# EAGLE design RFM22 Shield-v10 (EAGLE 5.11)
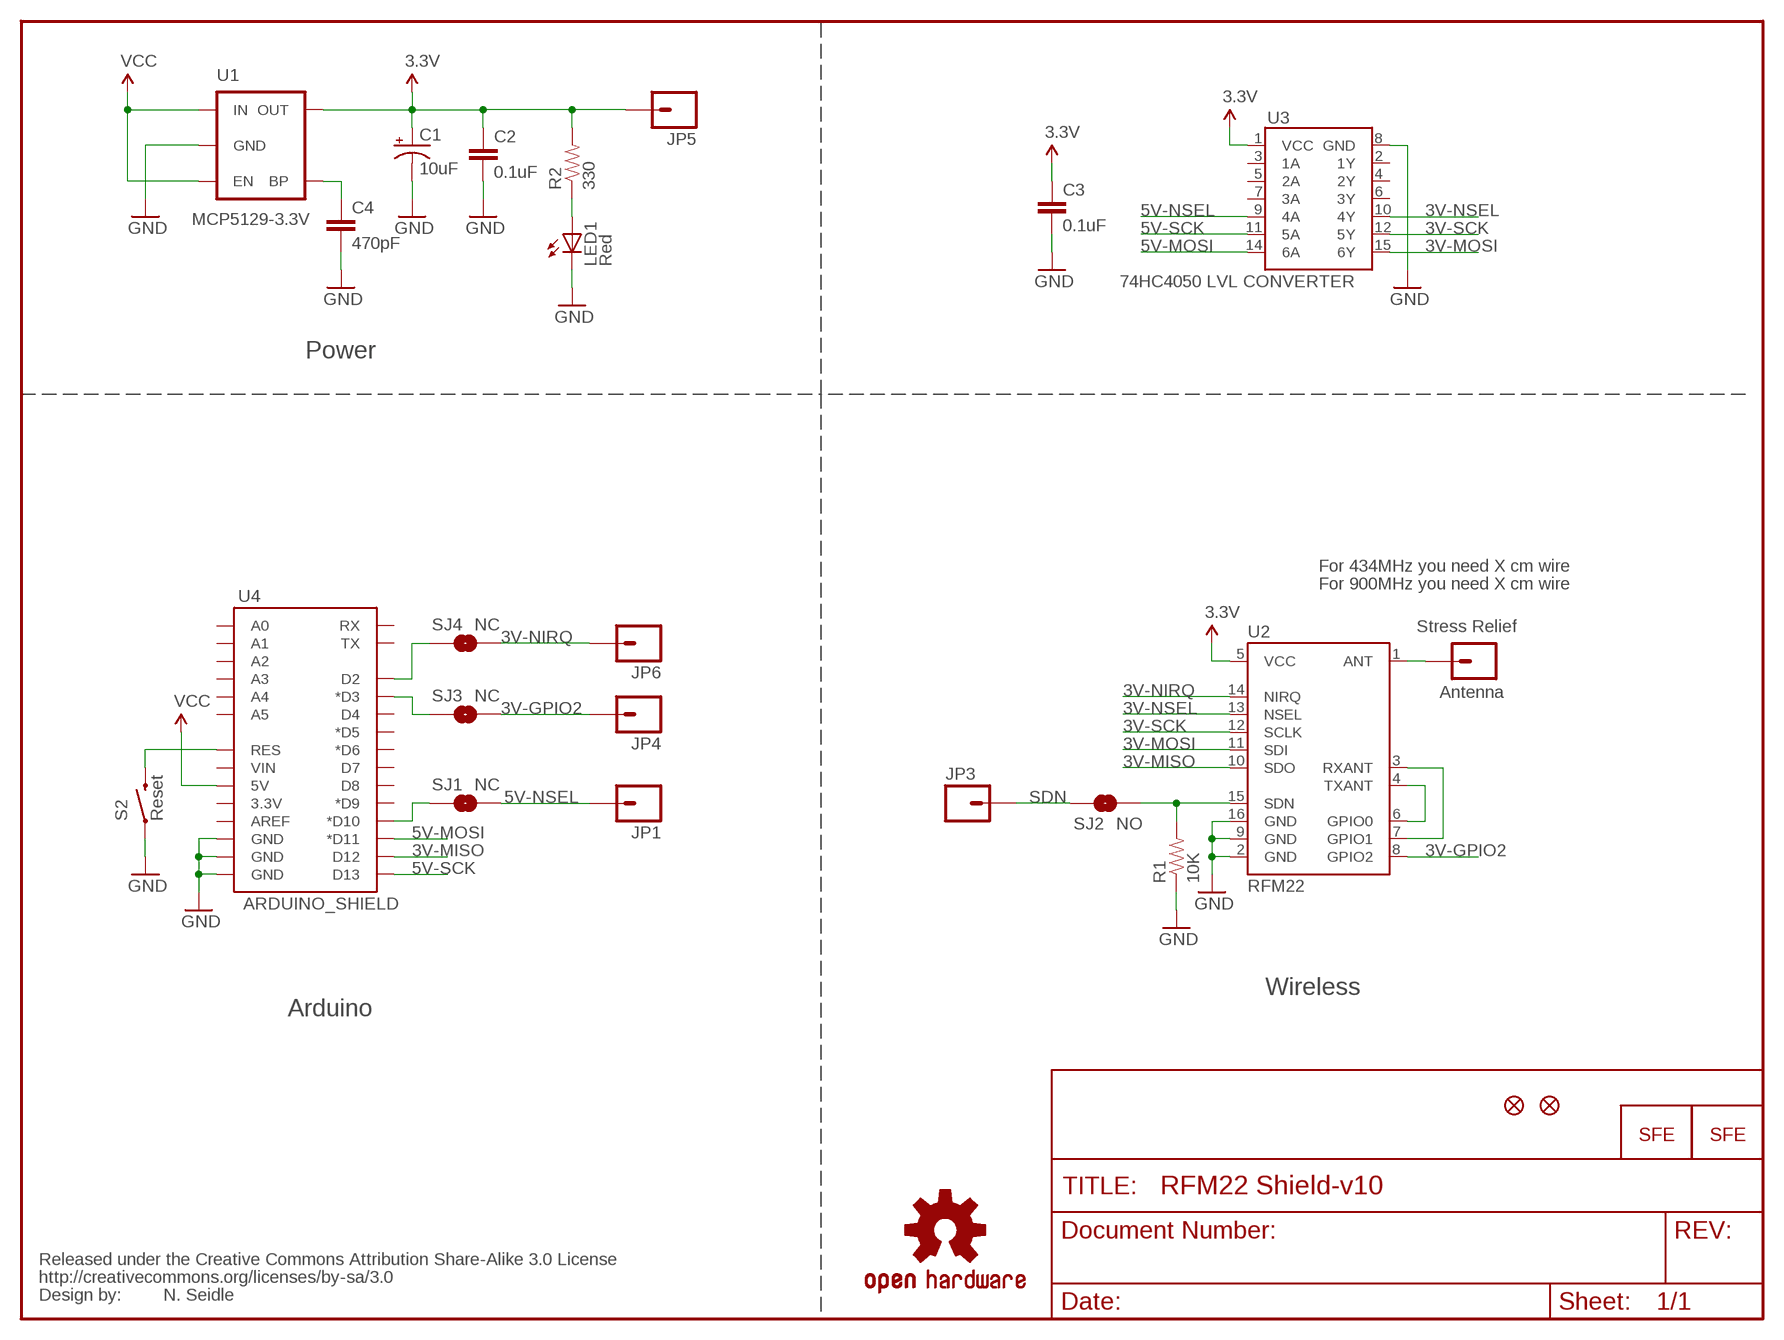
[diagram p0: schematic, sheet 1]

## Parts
C1  10uF  CAP_POL1206  [EIA3216]
C2  0.1uF  CAP0402-CAP  [0402-CAP]
C3  0.1uF  CAP0402-CAP  [0402-CAP]
C4  470pF  CAP0402-CAP  [0402-CAP]
JP1  M01PTH  [1X01]
JP2  Antenna  M01PTH  [1X01]
JP3  M01PTH  [1X01]
JP4  M01PTH  [1X01]
JP5  M01PTH  [1X01]
JP6  M01PTH  [1X01]
JP7  FIDUCIALUFIDUCIAL  [MICRO-FIDUCIAL]
JP8  FIDUCIALUFIDUCIAL  [MICRO-FIDUCIAL]
LED1  Red  LED0603  [LED-0603]
R1  10K  RESISTOR0402-RES  [0402-RES]
R2  330  RESISTOR0402-RES  [0402-RES]
S2  Reset  SWITCH-MOMENTARY-2SMD  [TACTILE_SWITCH_SMD]
SJ1  NC  SOLDERJUMPERTRACE  [SJ_2S-TRACE]
SJ2  NO  SOLDERJUMPERNO  [SJ_2S-NO]
SJ3  NC  SOLDERJUMPERTRACE  [SJ_2S-TRACE]
SJ4  NC  SOLDERJUMPERTRACE  [SJ_2S-TRACE]
U1  MCP5129-3.3V  V_REG_LDOSMD  [SOT23-5]
U2  RFM22  RFM22SMD  [RFM22-XXX-S2]
U3  74HC4050 LVL CONVERTER  HEX_CONVERTER  [SO016]
U4  ARDUINO_SHIELD  ARDUINO_SHIELDNOHOLES  [DUEMILANOVE_SHIELD_NOHOLES]
U$1  OSHW-LOGOS  [OSHW-LOGO-S]
U$3  CREATIVE_COMMONS  [CREATIVE_COMMONS]
U$7  LOGO-SFENEW  [SFE-NEW-WEBLOGO]
U$8  LOGO-SFENEW  [SFE-NEW-WEBLOGO]

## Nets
3.3V: C1.A(+) C2.1 C3.1 JP5.1 R2.2 U1.5(OUT) U2.5(VCC) U3.1(VCC)
3V-GPIO2: JP4.1 SJ3.2 U2.8(GPIO2)
3V-MISO: U2.10(SDO) U4.D12
3V-MOSI: U2.11(SDI) U3.15(6Y)
3V-NIRQ: JP6.1 SJ4.2 U2.14(NIRQ)
3V-NSEL: U2.13(NSEL) U3.10(4Y)
3V-SCK: U2.12(SCLK) U3.12(5Y)
5V-MOSI: U3.14(6A) U4.D11(*D11)
5V-NSEL: JP1.1 SJ1.2 U3.9(4A)
5V-SCK: U3.11(5A) U4.D13
ARST: S2.3 U4.RES
GND: C1.C(-) C2.2 C3.2 C4.2 LED1.C R1.1 S2.1 U1.2(GND) U2.2(GND) U2.9(GND) U2.16(GND) U3.8(GND) U4.GND@0(GND) U4.GND@1(GND) U4.GND@2(GND)
N$1: JP2.1 U2.1(ANT)
N$2: SJ1.1 U4.D10(*D10)
N$3: U2.4(TXANT) U2.6(GPIO0)
N$4: U2.3(RXANT) U2.7(GPIO1)
N$5: SJ3.1 U4.D3(*D3)
N$6: LED1.A R2.1
N$17: SJ4.1 U4.D2
N$70: C4.1 U1.4(BP)
SDN: JP3.1 SJ2.1
SDN2: R1.2 SJ2.2 U2.15(SDN)
VCC: U1.1(IN) U1.3(EN) U4.5V
Unconnected: U3.2(1Y) U3.3(1A) U3.4(2Y) U3.5(2A) U3.6(3Y) U3.7(3A) U4.3.3V U4.A0 U4.A1 U4.A2 U4.A3 U4.A4 U4.A5 U4.AREF U4.D4 U4.D5(*D5) U4.D6(*D6) U4.D7 U4.D8 U4.D9(*D9) U4.RX U4.TX U4.VIN

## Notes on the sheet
- Power
- For 434MHz you need X cm wire
- For 900MHz you need X cm wire
- Stress Relief
- Wireless
- Arduino
- N. Seidle

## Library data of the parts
C1 = SparkFun:CAP_POL: Capacitor Polarized
C2-C4 = SparkFun:CAP: Capacitor
JP1-JP6 = SparkFun:M01: Header 1
JP7 JP8 = SparkFun:FIDUCIAL: Fiducial Alignment Points
LED1 = SparkFun:LED: LEDs
R1 R2 = SparkFun:RESISTOR: Resistor
S2 = SparkFun:SWITCH-MOMENTARY-2
SJ1-SJ4 = SparkFun:SOLDERJUMPER: Solder Jumper
U1 = SparkFun:V_REG_LDO: Voltage Regulator LDO Standard 150mA LDO voltage regulator in SOT-23 layout. Micrel part MIC5205. BP (by-pass) pin is used to lower output noise with 470pF cap.
U2 = SparkFun:RFM22: Description: The RFM22 is a low-power, low cost radio that is capable of operating in the 434MHz and 900MHz open bands. It's frequency is software defined and there are some very good libraries written for it.
U3 = SparkFun:HEX_CONVERTER
U4 = SparkFun:ARDUINO_SHIELD
U$1 = SparkFun:OSHW-LOGO: Open Source Hardware Logo This logo indicates the piece of hardware it is found on incorporates a OSHW license and/or adheres to the definition of open source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
U$3 = SparkFun:CREATIVE_COMMONS
U$7 U$8 = SparkFun:LOGO-SFE: Spark Fun Electronics PCB Logo

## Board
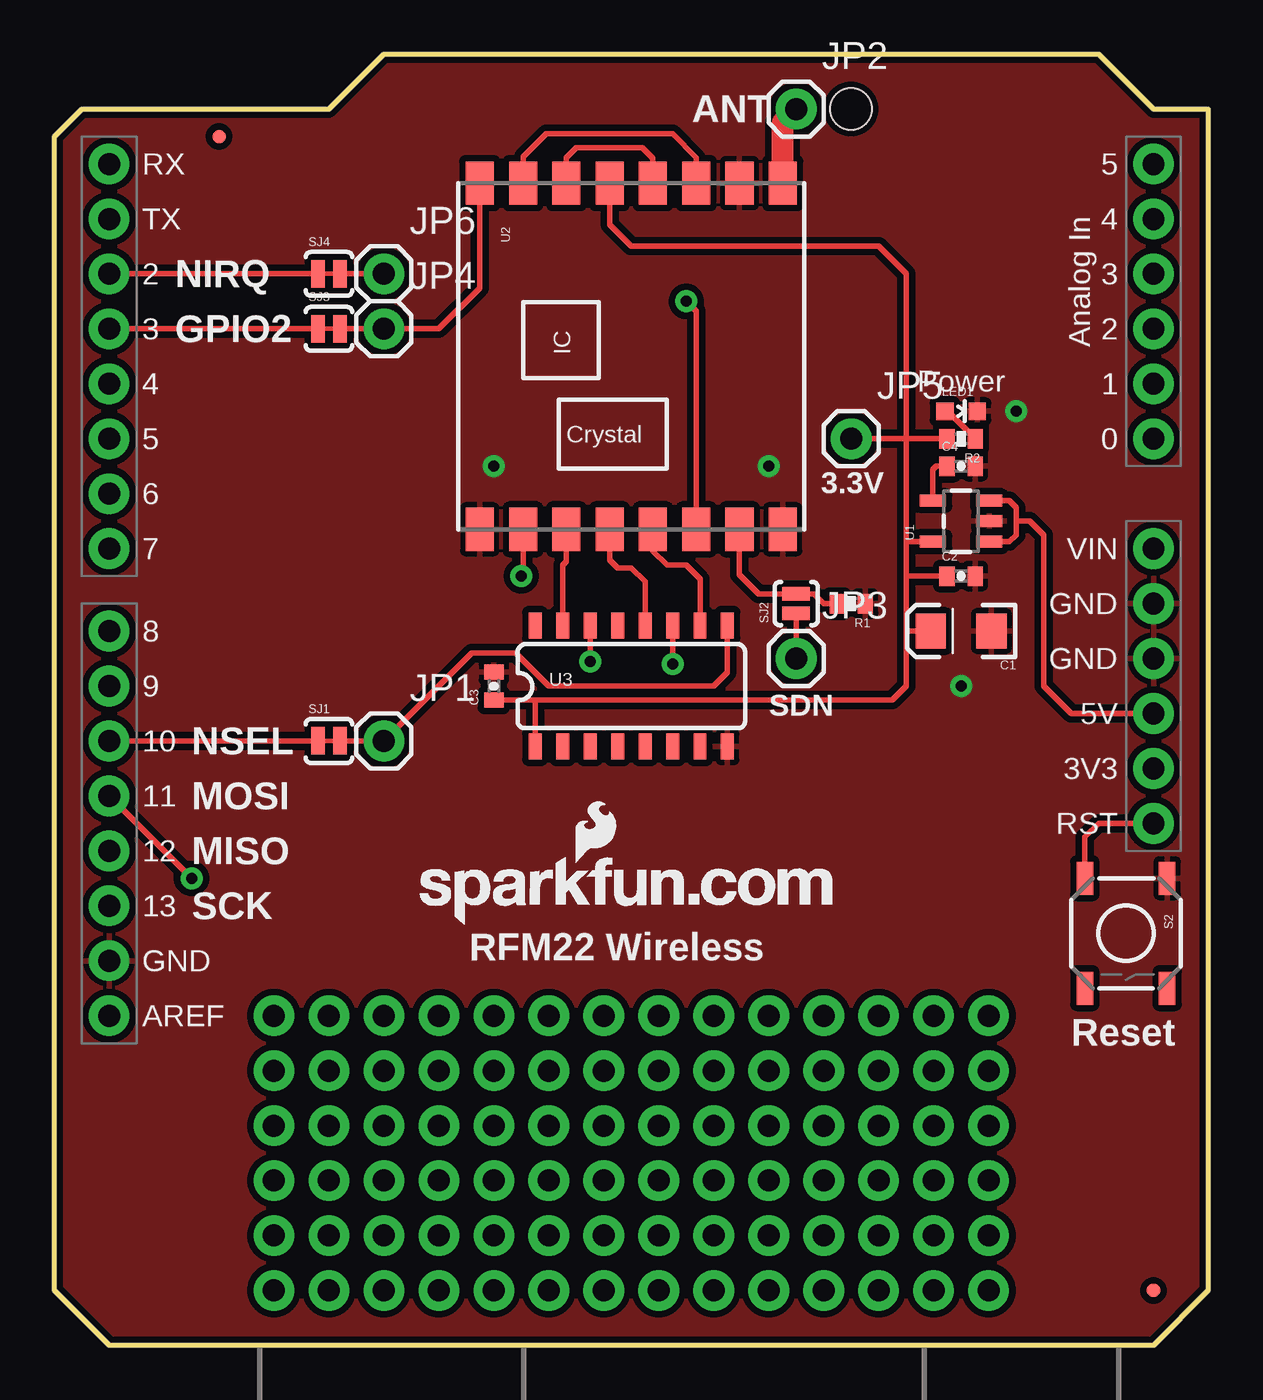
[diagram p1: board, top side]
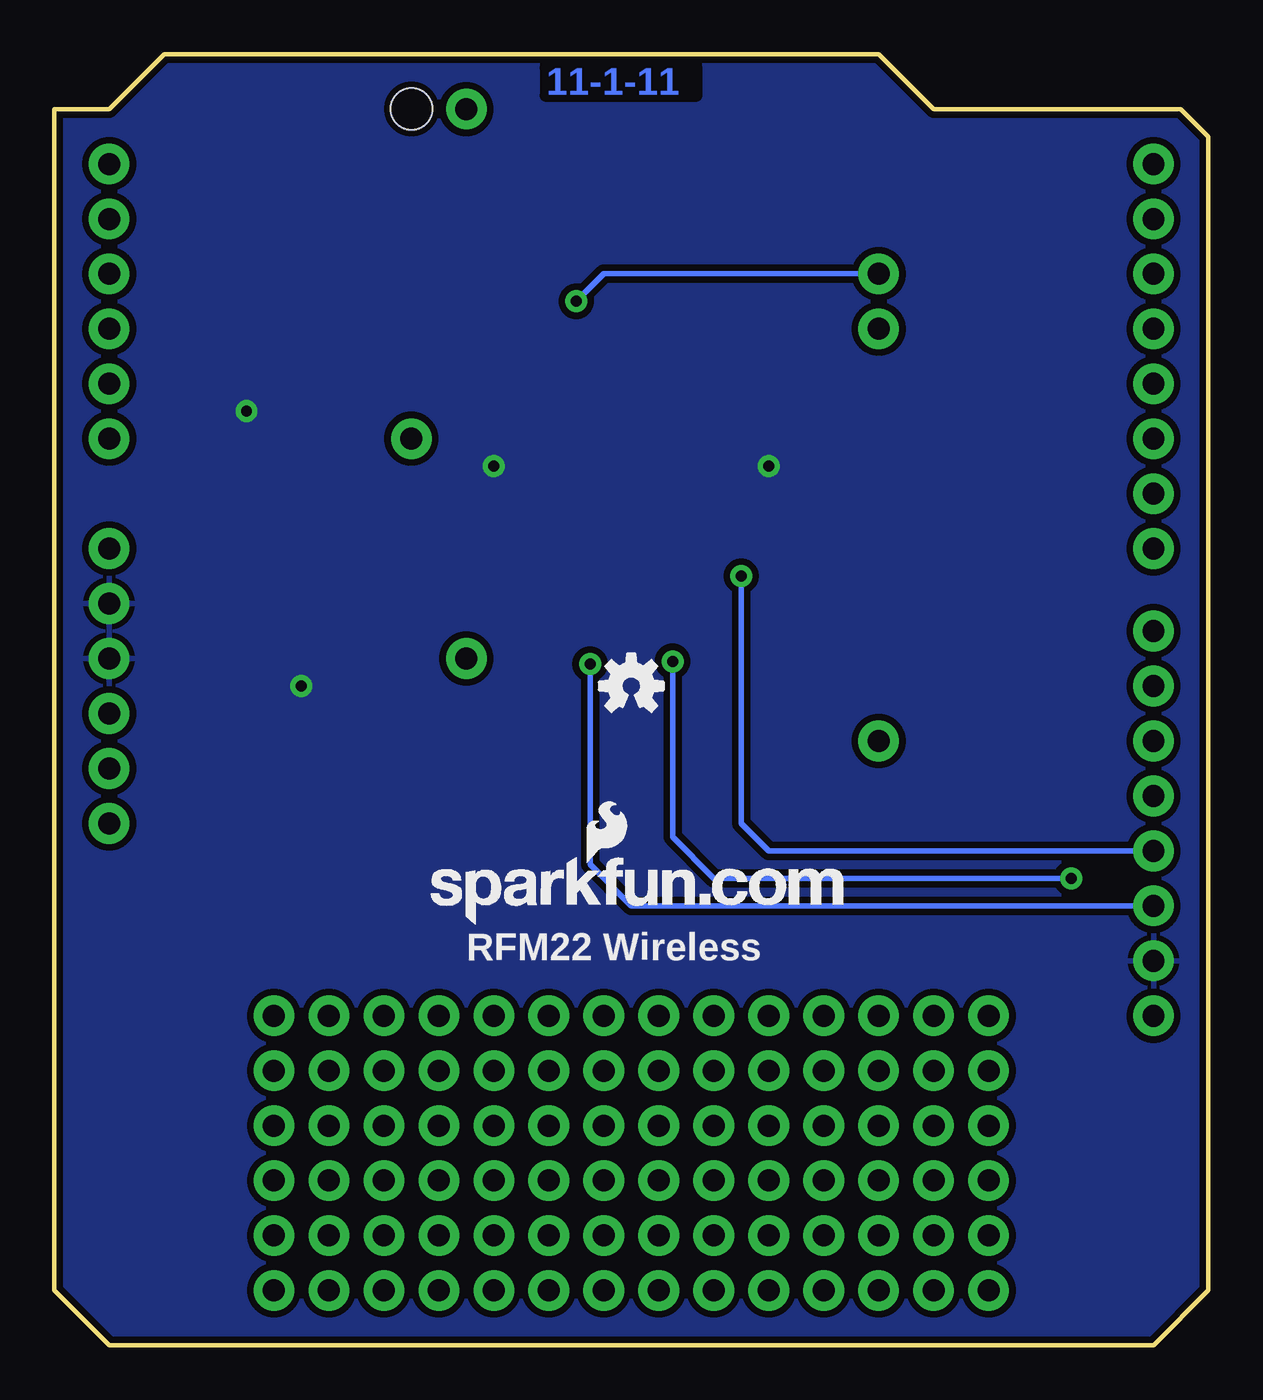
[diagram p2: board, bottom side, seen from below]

Size 53.34 x 59.69 mm. Coordinates in mm from the lower left corner, seen from the top.
Outline: 0,55.88 1.27,57.15 12.7,57.15 15.24,59.69 48.26,59.69 50.8,57.15 53.34,57.15 53.34,2.54 50.8,0 2.54,0 0,2.54 0,55.88
Copper layers (1*16): Top 0.035mm / dielectric 1.5mm / Bottom 0.035mm
Design rules "SparkFun": minimum track width 8mil, minimum drill 20mil, track to track 8mil, track to pad 8mil, pad to pad 8mil, via to via 8mil, smd to smd 8mil, copper to edge 10mil, drill to drill 8mil, minimum pad ring 12mil, minimum via ring 10mil, stop-mask expansion 4mil, vias tented up to drill 20mil, thermal gap 10mil
Holes 1.91 mm at 36.83,57.15

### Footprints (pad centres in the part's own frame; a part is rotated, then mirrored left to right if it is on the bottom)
EIA3216 = smd 1.4 x 1.6: A 1.4,0; C -1.4,0
0402-CAP = smd 0.7 x 0.9: 1 -0.65,0; 2 0.65,0
1X01 = drill 1.016 pad 1.88 round: 1 0,0
MICRO-FIDUCIAL = smd 0.635 x 0.635: 1 0,0
LED-0603 = smd 0.8 x 0.8: A 0,-0.75; C 0,0.75
0402-RES = smd 0.7 x 0.9: 1 -0.65,0; 2 0.65,0
TACTILE_SWITCH_SMD = smd 1.524 x 0.762: 1 -2.54,1.905; 2 2.54,1.905; 3 -2.54,-1.905; 4 2.54,-1.905
SJ_2S-TRACE = smd 0.635 x 1.27: 1 -0.508,0; 2 0.508,0
SJ_2S-NO = smd 0.635 x 1.27: 1 -0.45,0; 2 0.45,0
SOT23-5 = smd 0.55 x 1.2: 1 -0.95,-1.3; 2 0,-1.3; 3 0.95,-1.3; 4 0.95,1.3; 5 -0.95,1.3
RFM22-XXX-S2 = smd 2 x 1.3: 1 -8,7; 2 -8,5; 3 -8,3; 4 -8,1; 5 -8,-1; 6 -8,-3; 7 -8,-5; 8 -8,-7; 9 8,-7; 10 8,-5; 11 8,-3; 12 8,-1; 13 8,1; 14 8,3; 15 8,5; 16 8,7
SO016 = smd 0.6 x 1.2: 1 -4.445,-2.8; 2 -3.175,-2.8; 3 -1.905,-2.8; 4 -0.635,-2.8; 5 0.635,-2.8; 6 1.905,-2.8; 7 3.175,-2.8; 8 4.445,-2.8; 9 4.445,2.8; 10 3.175,2.8; 11 1.905,2.8; 12 0.635,2.8; 13 -0.635,2.8; 14 -1.905,2.8; 15 -3.175,2.8; 16 -4.445,2.8
DUEMILANOVE_SHIELD_NOHOLES = drill 1.016 pad 1.88 round: 3.3V 50.8,26.67; 5V 50.8,29.21; A0 50.8,41.91; A1 50.8,44.45; A2 50.8,46.99; A3 50.8,49.53; A4 50.8,52.07; A5 50.8,54.61; AREF 2.54,15.24; D2 2.54,49.53; D3 2.54,46.99; D4 2.54,44.45; D5 2.54,41.91; D6 2.54,39.37; D7 2.54,36.83; D8 2.54,33.02; D9 2.54,30.48; D10 2.54,27.94; D11 2.54,25.4; D12 2.54,22.86; D13 2.54,20.32; GND@0 50.8,31.75; GND@1 50.8,34.29; GND@2 2.54,17.78; RES 50.8,24.13; RX 2.54,54.61; TX 2.54,52.07; VIN 50.8,36.83

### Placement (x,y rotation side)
C1  41.91,33.02 180 top
C2  41.91,35.56 0 top
C3  20.32,30.48 90 top
C4  41.91,40.64 0 top
JP1  15.24,27.94 0 top
JP2  34.29,57.15 0 top
JP3  34.29,31.75 0 top
JP4  15.24,46.99 0 top
JP5  36.83,41.91 0 top
JP6  15.24,49.53 0 top
JP7  50.8,2.54 0 top
JP8  7.62,55.88 0 top
LED1  41.91,43.18 270 top
R1  36.83,34.29 180 top
R2  41.91,41.91 180 top
S2  49.53,19.05 270 top
SJ1  12.7,27.94 0 top
SJ2  34.29,34.29 90 top
SJ3  12.7,46.99 0 top
SJ4  12.7,49.53 0 top
U1  41.91,38.1 90 top
U2  26.67,45.72 270 top
U3  26.67,30.48 0 top
U4  0,0 0 top
U$1  26.67,30.48 0 bottom
U$3  not placed on the board
U$7  16.89,19.43 0 top
U$8  35.94,19.43 0 bottom

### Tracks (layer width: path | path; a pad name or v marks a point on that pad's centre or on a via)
3.3V
  Top 0.254: 39.37,33.02 39.37,35.56 | 39.37,35.56 39.37,37.21 | 39.37,33.02 C1.A | 39.37,35.56 C2.1 | U1.5 39.43,37.15 39.37,37.21 | 22.23,29.83 C3.1 | 22.23,29.83 38.72,29.83 39.37,30.48 39.37,33.02 | U3.1 22.23,29.83 | U2.5 25.67,51.8 26.67,50.8 38.1,50.8 39.37,49.53 39.37,41.91 | 39.37,37.21 39.37,41.91 | 39.37,41.91 R2.2 | 39.37,41.91 JP5.1
3V-GPIO2
  Top 0.254: U2.8 19.67,48.88 17.78,46.99 JP4.1 SJ3.2
3V-MISO  (via drill 0.51)
  Top 0.254: U2.10 21.67,35.64 v21.59,35.56
  Bottom 0.254: U4.D12 20.32,22.86 21.59,24.13 v21.59,35.56
3V-MOSI
  Top 0.254: U3.15 23.5,36.07 23.67,36.24 U2.11
3V-NIRQ  (via drill 0.51)
  Top 0.254: U2.14 29.67,47.8 v29.21,48.26 | SJ4.2 JP6.1
  Bottom 0.254: v29.21,48.26 27.94,49.53 JP6.1
3V-NSEL
  Top 0.254: U2.13 27.67,36.72 28.32,36.07 29.21,36.07 29.84,35.43 U3.10
3V-SCK
  Top 0.254: U2.12 25.67,36.31 26.04,35.94 26.67,35.94 27.3,35.31 U3.12
5V-MOSI  (via drill 0.51)
  Top 0.254: v24.77,31.62 U3.14 | v6.35,21.59 U4.D11
  Bottom 0.254: v24.77,31.62 24.77,23.5 22.86,21.59 v6.35,21.59
5V-NSEL
  Top 0.254: SJ1.2 JP1.1 19.3,32 21.34,32 22.86,30.48 30.48,30.48 31.11,31.11 U3.9
5V-SCK  (via drill 0.51)
  Top 0.254: v28.57,31.5 U3.11
  Bottom 0.254: U4.D13 26.67,20.32 28.57,22.23 v28.57,31.5
ARST
  Top 0.254: S2.3 47.62,23.5 48.26,24.13 U4.RES
GND  (via drill 0.51 pad 1.02)
  other vias: 20.32,40.64 33.02,40.64 41.91,30.48 44.45,43.18
  pour Top (isolate 0.305): 0,59.69 53.34,59.69 53.34,0 0,0
  pour Bottom (isolate 0.305): 0,0 0,59.69 53.34,59.69 53.34,0
N$1
  Top 1.016: U2.1 33.67,56.53 JP2.1
N$2
  Top 0.254: U4.D10 SJ1.1
N$3
  Top 0.254: U2.4 27.67,54.88 27.18,55.37 24.13,55.37 23.67,54.91 U2.6
N$4
  Top 0.254: U2.3 29.67,54.91 28.57,56.01 22.73,56.01 21.67,54.94 U2.7
N$5
  Top 0.254: U4.D3 SJ3.1
N$6
  Top 0.254: LED1.A 41.29,43.18 R2.1
N$7  (via drill 1.02 pad 1.88)
  other vias: 10.16,2.54
N$8  (via drill 1.02 pad 1.88)
  other vias: 10.16,5.08
N$9  (via drill 1.02 pad 1.88)
  other vias: 10.16,7.62
N$10  (via drill 1.02 pad 1.88)
  other vias: 12.7,2.54
N$11  (via drill 1.02 pad 1.88)
  other vias: 12.7,5.08
N$12  (via drill 1.02 pad 1.88)
  other vias: 12.7,7.62
N$13  (via drill 1.02 pad 1.88)
  other vias: 12.7,10.16
N$14  (via drill 1.02 pad 1.88)
  other vias: 10.16,10.16
N$15  (via drill 1.02 pad 1.88)
  other vias: 10.16,12.7
N$16  (via drill 1.02 pad 1.88)
  other vias: 10.16,15.24
N$17
  Top 0.254: U4.D2 SJ4.1
N$18  (via drill 1.02 pad 1.88)
  other vias: 12.7,12.7
N$19  (via drill 1.02 pad 1.88)
  other vias: 12.7,15.24
N$23  (via drill 1.02 pad 1.88)
  other vias: 15.24,2.54
N$24  (via drill 1.02 pad 1.88)
  other vias: 15.24,5.08
N$25  (via drill 1.02 pad 1.88)
  other vias: 15.24,7.62
N$26  (via drill 1.02 pad 1.88)
  other vias: 17.78,2.54
N$27  (via drill 1.02 pad 1.88)
  other vias: 17.78,5.08
N$28  (via drill 1.02 pad 1.88)
  other vias: 17.78,7.62
N$29  (via drill 1.02 pad 1.88)
  other vias: 17.78,10.16
N$30  (via drill 1.02 pad 1.88)
  other vias: 15.24,10.16
N$31  (via drill 1.02 pad 1.88)
  other vias: 20.32,2.54
N$32  (via drill 1.02 pad 1.88)
  other vias: 20.32,5.08
N$33  (via drill 1.02 pad 1.88)
  other vias: 20.32,7.62
N$34  (via drill 1.02 pad 1.88)
  other vias: 22.86,2.54
N$35  (via drill 1.02 pad 1.88)
  other vias: 22.86,5.08
N$36  (via drill 1.02 pad 1.88)
  other vias: 22.86,7.62
N$37  (via drill 1.02 pad 1.88)
  other vias: 22.86,10.16
N$38  (via drill 1.02 pad 1.88)
  other vias: 20.32,10.16
N$39  (via drill 1.02 pad 1.88)
  other vias: 25.4,2.54
N$40  (via drill 1.02 pad 1.88)
  other vias: 25.4,5.08
N$41  (via drill 1.02 pad 1.88)
  other vias: 25.4,7.62
N$42  (via drill 1.02 pad 1.88)
  other vias: 27.94,2.54
N$43  (via drill 1.02 pad 1.88)
  other vias: 27.94,5.08
N$44  (via drill 1.02 pad 1.88)
  other vias: 27.94,7.62
N$45  (via drill 1.02 pad 1.88)
  other vias: 27.94,10.16
N$46  (via drill 1.02 pad 1.88)
  other vias: 25.4,10.16
N$47  (via drill 1.02 pad 1.88)
  other vias: 30.48,2.54
N$48  (via drill 1.02 pad 1.88)
  other vias: 30.48,5.08
N$49  (via drill 1.02 pad 1.88)
  other vias: 30.48,7.62
N$50  (via drill 1.02 pad 1.88)
  other vias: 33.02,2.54
N$51  (via drill 1.02 pad 1.88)
  other vias: 33.02,5.08
N$52  (via drill 1.02 pad 1.88)
  other vias: 33.02,7.62
N$53  (via drill 1.02 pad 1.88)
  other vias: 33.02,10.16
N$54  (via drill 1.02 pad 1.88)
  other vias: 30.48,10.16
N$55  (via drill 1.02 pad 1.88)
  other vias: 35.56,2.54
N$56  (via drill 1.02 pad 1.88)
  other vias: 35.56,5.08
N$57  (via drill 1.02 pad 1.88)
  other vias: 35.56,7.62
N$58  (via drill 1.02 pad 1.88)
  other vias: 38.1,2.54
N$59  (via drill 1.02 pad 1.88)
  other vias: 38.1,5.08
N$60  (via drill 1.02 pad 1.88)
  other vias: 38.1,7.62
N$61  (via drill 1.02 pad 1.88)
  other vias: 38.1,10.16
N$62  (via drill 1.02 pad 1.88)
  other vias: 35.56,10.16
N$63  (via drill 1.02 pad 1.88)
  other vias: 40.64,2.54
N$64  (via drill 1.02 pad 1.88)
  other vias: 40.64,5.08
N$65  (via drill 1.02 pad 1.88)
  other vias: 40.64,7.62
N$66  (via drill 1.02 pad 1.88)
  other vias: 43.18,2.54
N$67  (via drill 1.02 pad 1.88)
  other vias: 43.18,5.08
N$68  (via drill 1.02 pad 1.88)
  other vias: 43.18,7.62
N$69  (via drill 1.02 pad 1.88)
  other vias: 43.18,10.16
N$70
  Top 0.254: U1.4 40.61,40.48 40.77,40.64 C4.1
N$71  (via drill 1.02 pad 1.88)
  other vias: 40.64,10.16
N$88  (via drill 1.02 pad 1.88)
  other vias: 15.24,12.7
N$89  (via drill 1.02 pad 1.88)
  other vias: 15.24,15.24
N$91  (via drill 1.02 pad 1.88)
  other vias: 17.78,12.7
N$92  (via drill 1.02 pad 1.88)
  other vias: 17.78,15.24
N$96  (via drill 1.02 pad 1.88)
  other vias: 20.32,12.7
N$97  (via drill 1.02 pad 1.88)
  other vias: 20.32,15.24
N$99  (via drill 1.02 pad 1.88)
  other vias: 22.86,12.7
N$100  (via drill 1.02 pad 1.88)
  other vias: 22.86,15.24
N$104  (via drill 1.02 pad 1.88)
  other vias: 25.4,12.7
N$105  (via drill 1.02 pad 1.88)
  other vias: 25.4,15.24
N$107  (via drill 1.02 pad 1.88)
  other vias: 27.94,12.7
N$108  (via drill 1.02 pad 1.88)
  other vias: 27.94,15.24
N$112  (via drill 1.02 pad 1.88)
  other vias: 30.48,12.7
N$113  (via drill 1.02 pad 1.88)
  other vias: 30.48,15.24
N$115  (via drill 1.02 pad 1.88)
  other vias: 33.02,12.7
N$116  (via drill 1.02 pad 1.88)
  other vias: 33.02,15.24
N$120  (via drill 1.02 pad 1.88)
  other vias: 35.56,12.7
N$121  (via drill 1.02 pad 1.88)
  other vias: 35.56,15.24
N$123  (via drill 1.02 pad 1.88)
  other vias: 38.1,12.7
N$124  (via drill 1.02 pad 1.88)
  other vias: 38.1,15.24
N$128  (via drill 1.02 pad 1.88)
  other vias: 40.64,12.7
N$129  (via drill 1.02 pad 1.88)
  other vias: 40.64,15.24
N$131  (via drill 1.02 pad 1.88)
  other vias: 43.18,12.7
N$132  (via drill 1.02 pad 1.88)
  other vias: 43.18,15.24
SDN
  Top 0.254: JP3.1 SJ2.1
SDN2
  Top 0.254: U2.15 31.67,35.64 32.57,34.74 SJ2.2 35.11,34.74 35.56,34.29 R1.2
VCC
  Top 0.254: U4.5V 46.99,29.21 45.72,30.48 45.72,37.47 45.09,38.1 44.45,38.1 | U1.3 44.13,39.05 44.45,38.73 44.45,38.1 | 44.45,38.1 44.45,37.47 44.13,37.15 U1.1

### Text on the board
Bottom: 11-1-11
tPlace: ANT | NIRQ | GPIO2 | Power | 3.3V | SDN | NSEL | MOSI | MISO | SCK | RFM22 Wireless | Reset | N. Seidle
bPlace: RFM22 Wireless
